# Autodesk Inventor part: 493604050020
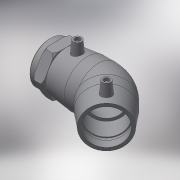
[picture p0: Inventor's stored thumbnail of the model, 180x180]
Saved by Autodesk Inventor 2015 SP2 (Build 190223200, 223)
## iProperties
Created: 2017-06
Part Number: 493604050020
Material: Generic
Description: PLASSON 45° ELBOW TRANSITION FEMALE 50-2"
Document SubType Name: Modeling
Designer: KIM
Mass: 264.747 g
Surface Area: 657.47 cm^2
Volume: 264.747 cm^3
Density: 1 g/cm^3
Appearance: Default
Author: KIM
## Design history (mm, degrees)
derived "493604.ipt"
feature "Solid1::493604.ipt"
tag "TaggingFeature1"
body "Solid1"
other parameters: "d2" = 67, "d4" = 31.25, "d5" = 60.3, "d8" = 168 deg, "d10" = 19.6, "d11" = 6.53333, "d29" = 51, "d30" = 15, "d31" = 43.75, "d34" = 5 deg, "d41" = 4, "d42" = 14, "d43" = 0, "d50" = 42.5, "d51" = 19.6, "d52" = 49, "d54" = 135 deg, "d86" = 30.15, "d87" = 135 deg, "d88" = 125, "d90" = 49, "d91" = 0, "d92" = 49, "d93" = 0, "d101" = 3, "d102" = 0, "d107" = 0.1, "d108" = 38, "d112" = 67, "d113" = 56.656, "d114" = 27, "d128" = 18, "d129" = 0, "d132" = 2.5, "d133" = 45 deg, "d134" = 45 deg, "d136" = 1.5, "L_" = 155, "L_1" = 49, "D_" = 38, "A_" = 51, "d_2" = 12, "Rp_" = 56.656, "D_1" = 67
